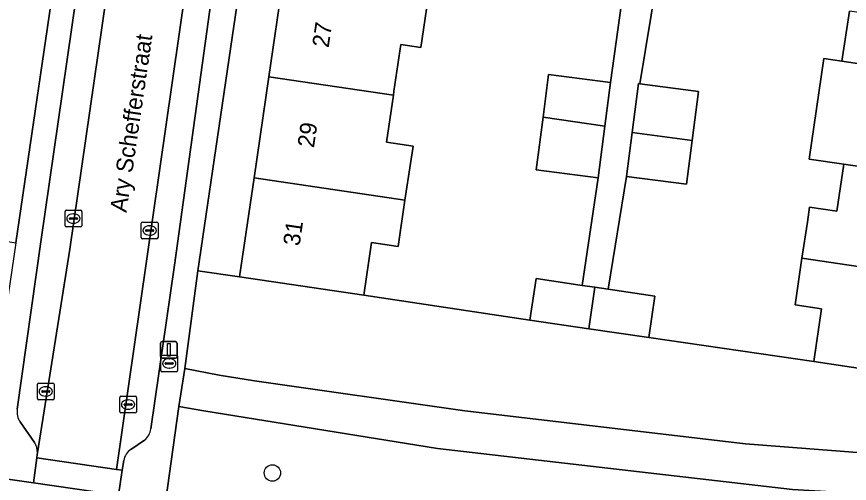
# Model space of a CAD drawing. Extents: x 163683 to 164494, y 382709 to 383872.
# Drawn here: x 164025.08 to 164074.8, y 382929.41 to 382957.25 of the extents above; entities that cross this region are included whole.
import ezdxf

# ---------------------------------------------------------------- set-up
doc = ezdxf.new("R2010")
doc.units = 0
for name, color, linetype in [('IMGEO_Boom', 7, 'Continuous'), ('IMGEO_Brandkraan', 7, 'Continuous'), ('IMGEO_Erf', 7, 'Continuous'), ('IMGEO_Fietspad_gesloten', 7, 'Continuous'), ('IMGEO_Groenvoorziening', 7, 'Continuous'), ('IMGEO_Kolk', 7, 'Continuous'), ('IMGEO_Lichtmast', 7, 'Continuous'), ('IMGEO_Openbare_ruimte_label', 7, 'Continuous'), ('IMGEO_Pand', 7, 'Continuous'), ('IMGEO_Pand_nummerreeks', 7, 'Continuous'), ('IMGEO_Parkeervlak_open', 7, 'Continuous'), ('IMGEO_Rijbaan_lokaal_open', 7, 'Continuous'), ('IMGEO_Voetpad_open', 7, 'Continuous')]:
    doc.layers.add(name, color=color, linetype=linetype)

msp = doc.modelspace()

# ---------------------------------------------------------------- linework, layer by layer
at = {"layer": 'IMGEO_Boom'}
msp.add_circle((164040.35, 382930.028), 0.489, dxfattribs=at)
at = {"layer": 'IMGEO_Brandkraan'}
for p, q in [((164033.694, 382936.139), (164033.694, 382936.991)), ((164033.769, 382937.065), (164034.621, 382937.065)), ((164034.182, 382936.845), (164034.207, 382936.845)), ((164034.695, 382936.991), (164034.695, 382936.139)), ((164033.953, 382936.559), (164033.953, 382936.571)), ((164034.391, 382936.522), (164033.993, 382936.522)), ((164033.996, 382936.608), (164034.394, 382936.608)), ((164034.205, 382936.285), (164034.18, 382936.285)), ((164034.437, 382936.571), (164034.437, 382936.559)), ((164034.621, 382936.065), (164033.769, 382936.065))]:
    msp.add_line(p, q, dxfattribs=at)
for points in [[(164033.694, 382936.139), (164033.694, 382936.991)], [(164033.769, 382937.065), (164034.621, 382937.065)], [(164034.695, 382936.991), (164034.695, 382936.139)], [(164034.621, 382936.065), (164033.769, 382936.065)]]:
    msp.add_lwpolyline(points, dxfattribs=at)
for centre, radius, start, end in [((164033.771, 382936.989), 0.0765, 91.552, 178.448), ((164033.771, 382936.989), 0.0765, 91.552, 178.448), ((164034.619, 382936.989), 0.0765, 1.552, 88.448), ((164034.619, 382936.989), 0.0765, 1.552, 88.448), ((164033.993, 382936.568), 0.0403, 85.8775, 175.7526), ((164033.99, 382936.558), 0.0366, 178.938, 274.7102), ((164034.394, 382936.565), 0.043, 264.8664, 352.4533), ((164034.398, 382936.57), 0.0386, 1.7309, 96.639), ((164033.771, 382936.141), 0.0765, 181.552, 268.448), ((164033.771, 382936.141), 0.0765, 181.552, 268.448), ((164034.619, 382936.141), 0.0765, 271.552, 358.448), ((164034.619, 382936.141), 0.0765, 271.552, 358.448)]:
    msp.add_arc(centre, radius, start, end, dxfattribs=at)
for centre, major_axis, ratio, start_param, end_param in [((164034.181, 382936.565), (-0.387, 0.002), 0.722429, 4.712389, 7.853982), ((164034.206, 382936.565), (-0.39, 0.002), 0.717154, 1.570796, 4.712389)]:
    msp.add_ellipse(centre, major_axis=major_axis, ratio=ratio, start_param=start_param, end_param=end_param, dxfattribs=at)
at = {"layer": 'IMGEO_Erf'}
for points in [[(164030.284, 382979.529), (164027.717, 382979.906), (164026.841, 382974.031), (164025.93, 382967.926), (164025.062, 382962.109), (164024.183, 382956.211), (164023.306, 382950.331), (164022.389, 382944.185), (164025.036, 382943.754)], [(164041.899, 382965.627), (164042.75, 382971.422), (164043.651, 382977.56), (164041.182, 382977.924), (164035.904, 382942.087), (164038.39, 382941.729), (164039.257, 382947.636), (164040.142, 382953.663), (164041.004, 382959.529)]]:
    msp.add_lwpolyline(points, close=True, dxfattribs=at)
for points in [[(164049.636, 382958.261), (164049.218, 382955.416), (164048.019, 382955.592), (164047.611, 382952.812), (164047.576, 382952.571), (164047.162, 382949.755), (164048.746, 382949.523), (164048.727, 382949.393), (164048.593, 382948.491), (164048.268, 382946.312), (164047.855, 382943.545), (164046.272, 382943.777), (164045.811, 382940.639), (164055.729, 382939.152), (164056.092, 382941.626), (164058.851, 382941.221), (164059.792, 382947.634), (164056.099, 382948.114), (164056.508, 382951.259), (164056.838, 382953.797), (164060.531, 382953.317), (164061.403, 382959.62)], [(164063.295, 382959.408), (164062.297, 382953.244), (164065.795, 382952.79), (164065.415, 382949.864), (164065.075, 382947.248), (164061.486, 382947.714), (164060.404, 382940.993), (164063.187, 382940.585), (164062.824, 382938.111), (164072.668, 382936.681), (164073.136, 382939.818), (164071.553, 382940.054), (164071.969, 382942.844), (164072.291, 382945), (164072.423, 382945.887), (164074.041, 382945.645), (164074.459, 382948.447), (164072.389, 382948.755), (164073.27, 382954.75), (164074.35, 382954.589), (164074.796, 382957.58)]]:
    msp.add_lwpolyline(points, dxfattribs=at)
at = {"layer": 'IMGEO_Fietspad_gesloten'}
msp.add_lwpolyline([(164045.501, 382922.94), (164040.344, 382925.695), (164038.227, 382926.732), (164033.962, 382928.278), (164031.173, 382928.704), (164026.085, 382929.437), (164023.007, 382929.886), (164022.216, 382930.007), (164020.136, 382929.862)], dxfattribs=at)
at = {"layer": 'IMGEO_Groenvoorziening'}
msp.add_lwpolyline([(164039.288, 382935.529), (164051.831, 382933.731), (164068.596, 382931.761), (164081.178, 382930.801), (164082.071, 382930.744), (164082.663, 382935.187), (164080.085, 382935.574), (164072.668, 382936.681), (164062.824, 382938.111), (164059.243, 382938.636), (164055.729, 382939.152), (164045.811, 382940.639), (164038.39, 382941.729), (164035.904, 382942.087), (164035.122, 382936.251), (164037.165, 382935.861)], close=True, dxfattribs=at)
msp.add_lwpolyline([(164071.17, 382920.18), (164075.274, 382921.115), (164077.448, 382921.353), (164080.709, 382921.39), (164081.754, 382928.429), (164080.74, 382928.493), (164071.398, 382929.032), (164050.201, 382931.494), (164036.256, 382933.735), (164034.772, 382933.986), (164033.962, 382928.278), (164038.227, 382926.732), (164040.344, 382925.695), (164045.501, 382922.94)], dxfattribs=at)
at = {"layer": 'IMGEO_Kolk'}
for p, q in [((164027.973, 382944.778), (164027.973, 382945.63)), ((164028.048, 382945.704), (164028.9, 382945.704)), ((164028.974, 382945.63), (164028.974, 382944.778)), ((164028.232, 382945.198), (164028.232, 382945.21)), ((164028.67, 382945.161), (164028.272, 382945.161)), ((164028.275, 382945.247), (164028.673, 382945.247)), ((164028.461, 382945.484), (164028.486, 382945.484)), ((164028.716, 382945.21), (164028.716, 382945.198)), ((164028.9, 382944.704), (164028.048, 382944.704)), ((164028.484, 382944.924), (164028.459, 382944.924)), ((164032.522, 382944.069), (164032.522, 382944.921)), ((164032.597, 382944.995), (164033.449, 382944.995)), ((164033.01, 382944.775), (164033.035, 382944.775)), ((164033.523, 382944.921), (164033.523, 382944.069)), ((164032.781, 382944.489), (164032.781, 382944.501)), ((164033.219, 382944.452), (164032.821, 382944.452)), ((164032.824, 382944.538), (164033.222, 382944.538)), ((164033.033, 382944.215), (164033.008, 382944.215)), ((164033.265, 382944.501), (164033.265, 382944.489)), ((164033.449, 382943.995), (164032.597, 382943.995)), ((164026.321, 382934.464), (164026.321, 382935.316)), ((164026.396, 382935.39), (164027.248, 382935.39)), ((164026.809, 382935.17), (164026.834, 382935.17)), ((164027.322, 382935.316), (164027.322, 382934.464)), ((164026.58, 382934.884), (164026.58, 382934.896)), ((164027.018, 382934.847), (164026.62, 382934.847)), ((164026.623, 382934.933), (164027.021, 382934.933)), ((164027.064, 382934.896), (164027.064, 382934.884)), ((164027.248, 382934.39), (164026.396, 382934.39)), ((164026.832, 382934.61), (164026.807, 382934.61)), ((164031.238, 382933.682), (164031.238, 382934.534)), ((164031.313, 382934.608), (164032.165, 382934.608)), ((164031.726, 382934.388), (164031.751, 382934.388)), ((164032.239, 382934.534), (164032.239, 382933.682)), ((164031.497, 382934.102), (164031.497, 382934.114)), ((164031.935, 382934.065), (164031.537, 382934.065)), ((164031.54, 382934.151), (164031.938, 382934.151)), ((164031.749, 382933.828), (164031.724, 382933.828)), ((164031.981, 382934.114), (164031.981, 382934.102)), ((164032.165, 382933.608), (164031.313, 382933.608))]:
    msp.add_line(p, q, dxfattribs=at)
for points in [[(164027.973, 382944.778), (164027.973, 382945.63)], [(164028.048, 382945.704), (164028.9, 382945.704)], [(164028.974, 382945.63), (164028.974, 382944.778)], [(164028.9, 382944.704), (164028.048, 382944.704)], [(164032.522, 382944.069), (164032.522, 382944.921)], [(164032.597, 382944.995), (164033.449, 382944.995)], [(164033.523, 382944.921), (164033.523, 382944.069)], [(164033.449, 382943.995), (164032.597, 382943.995)], [(164026.321, 382934.464), (164026.321, 382935.316)], [(164026.396, 382935.39), (164027.248, 382935.39)], [(164027.322, 382935.316), (164027.322, 382934.464)], [(164027.248, 382934.39), (164026.396, 382934.39)], [(164031.238, 382933.682), (164031.238, 382934.534)], [(164031.313, 382934.608), (164032.165, 382934.608)], [(164032.239, 382934.534), (164032.239, 382933.682)], [(164032.165, 382933.608), (164031.313, 382933.608)]]:
    msp.add_lwpolyline(points, dxfattribs=at)
for centre, radius, start, end in [((164028.05, 382945.628), 0.0765, 91.552, 178.448), ((164028.05, 382945.628), 0.0765, 91.552, 178.448), ((164028.898, 382945.628), 0.0765, 1.552, 88.448), ((164028.898, 382945.628), 0.0765, 1.552, 88.448), ((164028.272, 382945.207), 0.0403, 85.8775, 175.7526), ((164028.269, 382945.197), 0.0366, 178.938, 274.7102), ((164028.673, 382945.204), 0.043, 264.8664, 352.4533), ((164028.677, 382945.209), 0.0386, 1.7309, 96.639), ((164028.05, 382944.78), 0.0765, 181.552, 268.448), ((164028.05, 382944.78), 0.0765, 181.552, 268.448), ((164028.898, 382944.78), 0.0765, 271.552, 358.448), ((164028.898, 382944.78), 0.0765, 271.552, 358.448), ((164032.599, 382944.919), 0.0765, 91.552, 178.448), ((164032.599, 382944.919), 0.0765, 91.552, 178.448), ((164033.447, 382944.919), 0.0765, 1.552, 88.448), ((164033.447, 382944.919), 0.0765, 1.552, 88.448), ((164032.821, 382944.498), 0.0403, 85.8775, 175.7526), ((164032.818, 382944.488), 0.0366, 178.938, 274.7102), ((164033.222, 382944.495), 0.043, 264.8664, 352.4533), ((164033.226, 382944.5), 0.0386, 1.7309, 96.639), ((164032.599, 382944.071), 0.0765, 181.552, 268.448), ((164032.599, 382944.071), 0.0765, 181.552, 268.448), ((164033.447, 382944.071), 0.0765, 271.552, 358.448), ((164033.447, 382944.071), 0.0765, 271.552, 358.448), ((164026.398, 382935.314), 0.0765, 91.552, 178.448), ((164026.398, 382935.314), 0.0765, 91.552, 178.448), ((164027.246, 382935.314), 0.0765, 1.552, 88.448), ((164027.246, 382935.314), 0.0765, 1.552, 88.448), ((164026.62, 382934.893), 0.0403, 85.8775, 175.7526), ((164026.617, 382934.883), 0.0366, 178.938, 274.7102), ((164027.021, 382934.89), 0.043, 264.8664, 352.4533), ((164027.025, 382934.895), 0.0386, 1.7309, 96.639), ((164026.398, 382934.466), 0.0765, 181.552, 268.448), ((164026.398, 382934.466), 0.0765, 181.552, 268.448), ((164027.246, 382934.466), 0.0765, 271.552, 358.448), ((164027.246, 382934.466), 0.0765, 271.552, 358.448), ((164031.315, 382934.532), 0.0765, 91.552, 178.448), ((164031.315, 382934.532), 0.0765, 91.552, 178.448), ((164032.163, 382934.532), 0.0765, 1.552, 88.448), ((164032.163, 382934.532), 0.0765, 1.552, 88.448), ((164031.315, 382933.684), 0.0765, 181.552, 268.448), ((164031.315, 382933.684), 0.0765, 181.552, 268.448), ((164031.537, 382934.111), 0.0403, 85.8775, 175.7526), ((164031.534, 382934.101), 0.0366, 178.938, 274.7102), ((164031.938, 382934.108), 0.043, 264.8664, 352.4533), ((164031.942, 382934.113), 0.0386, 1.7309, 96.639), ((164032.163, 382933.684), 0.0765, 271.552, 358.448), ((164032.163, 382933.684), 0.0765, 271.552, 358.448)]:
    msp.add_arc(centre, radius, start, end, dxfattribs=at)
for centre, major_axis, ratio, start_param, end_param in [((164028.46, 382945.204), (-0.387, 0.002), 0.722429, 4.712389, 7.853982), ((164028.485, 382945.204), (-0.39, 0.002), 0.717154, 1.570796, 4.712389), ((164033.009, 382944.495), (-0.387, 0.002), 0.722429, 4.712389, 7.853982), ((164033.034, 382944.495), (-0.39, 0.002), 0.717154, 1.570796, 4.712389), ((164026.808, 382934.89), (-0.387, 0.002), 0.722429, 4.712389, 7.853982), ((164026.833, 382934.89), (-0.39, 0.002), 0.717154, 1.570796, 4.712389), ((164031.725, 382934.108), (-0.387, 0.002), 0.722429, 4.712389, 7.853982), ((164031.75, 382934.108), (-0.39, 0.002), 0.717154, 1.570796, 4.712389)]:
    msp.add_ellipse(centre, major_axis=major_axis, ratio=ratio, start_param=start_param, end_param=end_param, dxfattribs=at)
at = {"layer": 'IMGEO_Lichtmast'}
for p, q in [((164033.671, 382936.968), (164033.671, 382937.768)), ((164033.671, 382937.768), (164033.671, 382936.968)), ((164033.771, 382937.868), (164034.561, 382937.868)), ((164034.561, 382937.868), (164033.771, 382937.868)), ((164034.661, 382937.768), (164034.661, 382936.968)), ((164034.661, 382936.968), (164034.661, 382937.768)), ((164034.561, 382936.868), (164033.771, 382936.868)), ((164033.771, 382936.868), (164034.561, 382936.868))]:
    msp.add_line(p, q, dxfattribs=at)
msp.add_lwpolyline([(164034.091, 382937.743), (164034.241, 382937.743), (164034.241, 382936.993), (164034.091, 382936.993), (164034.091, 382937.743)], dxfattribs=at)
for centre, start, end in [((164033.771, 382937.768), 90, 180), ((164033.771, 382937.768), 90, 180), ((164034.561, 382937.768), 0, 90), ((164034.561, 382937.768), 360, 90), ((164033.771, 382936.968), 180, 270), ((164033.771, 382936.968), 180, 270), ((164034.561, 382936.968), 270, 0), ((164034.561, 382936.968), 270, 0)]:
    msp.add_arc(centre, 0.1, start, end, dxfattribs=at)
at = {"layer": 'IMGEO_Pand'}
for points in [[(164074.35, 382954.589), (164082.735, 382953.339), (164083.64, 382959.406), (164076.242, 382960.509), (164075.783, 382957.433), (164074.796, 382957.58)], [(164048.019, 382955.592), (164049.218, 382955.416), (164049.636, 382958.261), (164041.004, 382959.529), (164040.142, 382953.663), (164047.576, 382952.571), (164047.611, 382952.812)], [(164074.35, 382954.589), (164073.27, 382954.75), (164072.389, 382948.755), (164074.459, 382948.447), (164081.841, 382947.347), (164082.735, 382953.339)], [(164047.576, 382952.571), (164040.142, 382953.663), (164039.257, 382947.636), (164048.268, 382946.312), (164048.593, 382948.491), (164048.727, 382949.393), (164048.746, 382949.523), (164047.162, 382949.755)], [(164060.193, 382950.718), (164060.531, 382953.317), (164056.838, 382953.797), (164056.508, 382951.259)], [(164062.297, 382953.244), (164062.206, 382953.256), (164061.826, 382950.33), (164065.415, 382949.864), (164065.795, 382952.79)], [(164060.193, 382950.718), (164056.508, 382951.259), (164056.099, 382948.114), (164059.792, 382947.634)], [(164065.415, 382949.864), (164061.826, 382950.33), (164061.486, 382947.714), (164065.075, 382947.248)], [(164081.841, 382947.347), (164074.459, 382948.447), (164074.041, 382945.645), (164072.423, 382945.887), (164072.291, 382945), (164071.969, 382942.844), (164080.969, 382941.503)], [(164048.268, 382946.312), (164039.257, 382947.636), (164038.39, 382941.729), (164045.811, 382940.639), (164046.272, 382943.777), (164047.855, 382943.545)], [(164071.969, 382942.844), (164071.553, 382940.054), (164073.136, 382939.818), (164072.668, 382936.681), (164080.085, 382935.574), (164080.969, 382941.503)], [(164059.609, 382941.11), (164058.851, 382941.221), (164056.092, 382941.626), (164055.729, 382939.152), (164059.243, 382938.636)], [(164063.187, 382940.585), (164060.404, 382940.993), (164059.609, 382941.11), (164059.243, 382938.636), (164062.824, 382938.111)]]:
    msp.add_lwpolyline(points, close=True, dxfattribs=at)
at = {"layer": 'IMGEO_Parkeervlak_open'}
for points in [[(164026.328, 382931.232), (164028.267, 382943.381), (164033.312, 382978.332), (164033.399, 382978.926), (164032.73, 382977.955), (164031.704, 382977.164)], [(164037.934, 382978.093), (164037.869, 382977.652), (164032.837, 382942.654), (164031.035, 382930.239), (164031.379, 382930.188), (164031.475, 382930.779)], [(164031.25, 382976.464), (164026.518, 382943.815), (164025.123, 382933.834)], [(164033.1, 382932.664), (164034.507, 382942.427), (164039.063, 382975.361)], [(164025.291, 382933.072), (164026.146, 382931.85)], [(164031.904, 382931.431), (164032.714, 382931.986)]]:
    msp.add_lwpolyline(points, dxfattribs=at)
for centre, radius, start, end in [((164026.099, 382933.65), 0.993, 169.3052, 215.5612), ((164032.027, 382932.826), 1.085, 309.272, 351.4204), ((164025.197, 382931.235), 1.131, 359.8629, 32.9564), ((164032.469, 382930.592), 1.011, 123.9499, 169.3622)]:
    msp.add_arc(centre, radius, start, end, dxfattribs=at)
at = {"layer": 'IMGEO_Rijbaan_lokaal_open'}
for points in [[(164031.035, 382930.239), (164032.837, 382942.654), (164037.869, 382977.652), (164033.312, 382978.332), (164028.267, 382943.381), (164026.328, 382931.232), (164026.311, 382931.123), (164026.287, 382930.934)], [(164031.035, 382930.239), (164026.287, 382930.934), (164026.085, 382929.437), (164031.173, 382928.704), (164031.379, 382930.188)]]:
    msp.add_lwpolyline(points, close=True, dxfattribs=at)
at = {"layer": 'IMGEO_Voetpad_open'}
for points in [[(164042.552, 383044.282), (164040.359, 383044.602), (164040.159, 383043.219), (164039.085, 383035.797), (164039.946, 383035.673), (164039.652, 383033.645), (164038.176, 383023.49), (164037.66, 383019.957), (164036.238, 383020.151), (164035.986, 383018.399), (164033.287, 383000), (164030.709, 382982.425), (164030.284, 382979.529), (164025.036, 382943.754), (164024.242, 382938.326), (164023.876, 382935.821), (164023.007, 382929.886), (164026.085, 382929.437), (164026.287, 382930.934), (164026.311, 382931.123), (164026.328, 382931.232)], [(164031.475, 382930.779), (164031.379, 382930.188), (164031.173, 382928.704), (164033.962, 382928.278), (164034.772, 382933.986), (164035.122, 382936.251), (164035.904, 382942.087), (164041.182, 382977.924), (164041.604, 382980.786), (164044.434, 383000), (164046.905, 383016.783), (164047.16, 383018.512), (164045.727, 383018.722), (164046.251, 383022.297), (164048.048, 383034.593)], [(164025.123, 382933.834), (164026.518, 382943.815), (164031.25, 382976.464)], [(164039.063, 382975.361), (164034.507, 382942.427), (164033.1, 382932.664)], [(164061.403, 382959.62), (164060.531, 382953.317), (164060.193, 382950.718), (164059.792, 382947.634), (164058.851, 382941.221), (164059.609, 382941.11), (164060.404, 382940.993), (164061.486, 382947.714), (164061.826, 382950.33), (164062.206, 382953.256), (164062.297, 382953.244), (164063.295, 382959.408)], [(164026.146, 382931.85), (164025.291, 382933.072)], [(164032.714, 382931.986), (164031.904, 382931.431)]]:
    msp.add_lwpolyline(points, dxfattribs=at)
msp.add_lwpolyline([(164080.74, 382928.493), (164081.754, 382928.429), (164082.071, 382930.744), (164081.178, 382930.801), (164068.596, 382931.761), (164051.831, 382933.731), (164039.288, 382935.529), (164037.165, 382935.861), (164035.122, 382936.251), (164034.772, 382933.986), (164036.256, 382933.735), (164050.201, 382931.494), (164071.398, 382929.032)], close=True, dxfattribs=at)
for centre, radius, start, end in [((164026.099, 382933.65), 0.993, 169.3052, 215.5612), ((164032.027, 382932.826), 1.085, 309.272, 351.4204), ((164025.197, 382931.235), 1.131, 359.8629, 32.9564), ((164032.469, 382930.592), 1.011, 123.9499, 169.3622)]:
    msp.add_arc(centre, radius, start, end, dxfattribs=at)

# ---------------------------------------------------------------- texts
at = {"layer": 'IMGEO_Openbare_ruimte_label'}
msp.add_text('Ary Schefferstraat', height=1, rotation=81.6591, dxfattribs=at).set_placement((164031.639, 382945.534))
at = {"layer": 'IMGEO_Pand_nummerreeks'}
for s, rotation, p in [('27', 81.6465, (164043.707, 382955.364)), ('29', 81.6465, (164042.83, 382949.392)), ('31', 81.647, (164041.971, 382943.533))]:
    msp.add_text(s, height=1, rotation=rotation, dxfattribs=at).set_placement(p)

doc.saveas('drawing.dxf')
